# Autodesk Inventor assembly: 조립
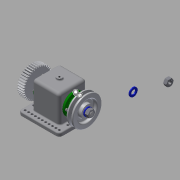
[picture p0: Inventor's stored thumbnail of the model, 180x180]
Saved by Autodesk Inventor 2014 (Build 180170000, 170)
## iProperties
Created: 2018-11
Part Number: 조립
Document SubType Name: Assembly
Designer: kh
Author: kh
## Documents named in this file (13)
- C:\Users\kh\Desktop\481107V1021\조립.iam
- C:\Users\kh\Desktop\481107V1021\본체.ipt
- C:\Users\kh\Desktop\481107V1021\V벨트풀리.ipt
- C:\Users\kh\Desktop\481107V1021\너트 M12x1.25.ipt
- C:\Users\kh\Desktop\481107V1021\베어링 6203.ipt
- C:\Users\kh\Desktop\481107V1021\볼트 M4.ipt
- C:\Users\kh\Desktop\481107V1021\부시.ipt
- C:\Users\kh\Desktop\481107V1021\스퍼기어.ipt
- C:\Users\kh\Desktop\481107V1021\오일 실 26 38 8.ipt
- C:\Users\kh\Desktop\481107V1021\와셔 12x24.ipt
- C:\Users\kh\Desktop\481107V1021\축.ipt
- C:\Users\kh\Desktop\481107V1021\커버.ipt
- C:\Users\kh\Desktop\481107V1021\키 5x5x12.ipt
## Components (1 placed, 1 different names)
1. V벨트풀리:1
